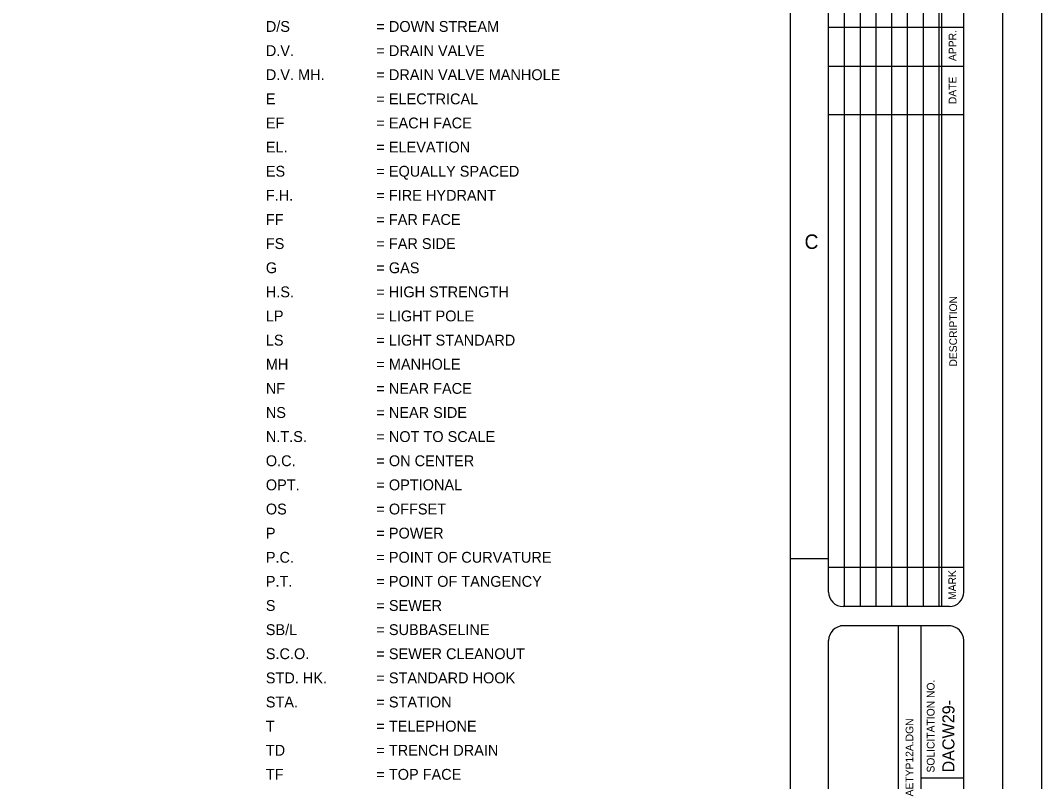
# Model space of a CAD drawing. Extents: x 22369.62 to 22373.29, y 22369.62 to 22372.46.
# Drawn here: x 22372.185 to 22373.288, y 22370.797 to 22371.619 of the extents above; entities that cross this region are included whole.
import ezdxf

# ---------------------------------------------------------------- set-up
doc = ezdxf.new("R2010")
doc.units = 0
for name, color, linetype in [('Level 1', 7, 'Continuous'), ('Level 10', 7, 'Continuous'), ('Level 2', 7, 'Continuous'), ('Level 4', 7, 'Continuous'), ('Level 7', 7, 'Continuous'), ('Level 9', 7, 'Continuous')]:
    doc.layers.add(name, color=color, linetype=linetype)

msp = doc.modelspace()

# ---------------------------------------------------------------- linework, layer by layer
at = {"layer": 'Level 1'}
for p, q in [((22373.075, 22372.2363), (22373.075, 22370.9863)), ((22373.092, 22372.2363), (22373.092, 22370.9863)), ((22373.109, 22372.2363), (22373.109, 22370.9863)), ((22373.126, 22372.2363), (22373.126, 22370.9863)), ((22373.143, 22372.2363), (22373.143, 22370.9863)), ((22373.16, 22372.2363), (22373.16, 22370.9863)), ((22373.177, 22372.2363), (22373.177, 22370.9863)), ((22373.18, 22372.2363), (22373.18, 22370.9863)), ((22373.204, 22371.6113), (22373.058, 22371.6113)), ((22373.1884, 22370.9863), (22373.0736, 22370.9863)), ((22373.19, 22370.9653), (22373.071, 22370.9653)), ((22373.133, 22370.9653), (22373.133, 22370.2673))]:
    msp.add_line(p, q, dxfattribs=at)
msp.add_lwpolyline([(22369.6213, 22372.4553), (22373.288, 22372.4553), (22373.288, 22369.6213), (22369.6213, 22369.6213)], close=True, dxfattribs=at)
for points in [[(22373.058, 22371.0019), (22373.058, 22372.2207)], [(22373.204, 22371.0019), (22373.204, 22372.2207)], [(22373.1884, 22370.9653), (22373.0736, 22370.9653)], [(22373.058, 22370.2829), (22373.058, 22370.9497)], [(22373.204, 22370.2829), (22373.204, 22370.9497)]]:
    msp.add_lwpolyline(points, dxfattribs=at)
for centre, start, end in [((22373.0736, 22371.0019), 180, 270), ((22373.1884, 22371.0019), 270, 0), ((22373.0736, 22370.9497), 90, 180), ((22373.1884, 22370.9497), 0, 90)]:
    msp.add_arc(centre, 0.0156, start, end, dxfattribs=at)
at = {"layer": 'Level 10'}
msp.add_line((22373.017, 22371.0383), (22373.058, 22371.0383), dxfattribs=at)
at = {"layer": 'Level 2'}
for p, q in [((22373.1576, 22370.9653), (22373.1576, 22370.6163)), ((22373.204, 22370.801), (22373.1576, 22370.801))]:
    msp.add_line(p, q, dxfattribs=at)
at = {"layer": 'Level 7'}
for p, q in [((22373.204, 22371.5693), (22373.058, 22371.5693)), ((22373.204, 22371.5172), (22373.058, 22371.5172)), ((22373.204, 22371.0283), (22373.058, 22371.0283))]:
    msp.add_line(p, q, dxfattribs=at)
at = {"layer": 'Level 9'}
msp.add_line((22373.246, 22369.6633), (22373.246, 22372.4133), dxfattribs=at)
msp.add_lwpolyline([(22373.017, 22369.6633), (22373.017, 22372.4133)], dxfattribs=at)

# ---------------------------------------------------------------- texts
at = {"layer": 'Level 1'}
for s, height, p in [('APPR.', 0.00833, (22373.196, 22371.5751)), ('DATE', 0.00833, (22373.196, 22371.5286)), ('DESCRIPTION', 0.008333, (22373.1967, 22371.2453)), ('MARK', 0.00833, (22373.1957, 22370.9934)), ('SOLICITATION NO.', 0.008334, (22373.1724, 22370.8071)), ('AETYP12A.DGN', 0.008333, (22373.1495, 22370.7813))]:
    msp.add_text(s, height=height, rotation=90, dxfattribs=at).set_placement(p)
msp.add_text('C', height=0.0156, dxfattribs=at).set_placement((22373.032, 22371.3723))
at = {"layer": 'Level 4'}
for s, height, p in [('D/S', 0.0117, (22372.4503, 22371.6066)), ('= DOWN STREAM', 0.011698, (22372.5697, 22371.6066)), ('D.V.', 0.0117, (22372.4503, 22371.5805)), ('= DRAIN VALVE', 0.011698, (22372.5697, 22371.5805)), ('D.V. MH.', 0.0117, (22372.4503, 22371.5545)), ('= DRAIN VALVE MANHOLE', 0.011698, (22372.5697, 22371.5545)), ('E', 0.0117, (22372.4503, 22371.5284)), ('= ELECTRICAL', 0.011698, (22372.5697, 22371.5284)), ('EF', 0.0117, (22372.4503, 22371.5024)), ('= EACH FACE', 0.011698, (22372.5697, 22371.5024)), ('EL.', 0.0117, (22372.4503, 22371.4764)), ('= ELEVATION', 0.011698, (22372.5697, 22371.4764)), ('ES ', 0.0117, (22372.4503, 22371.4503)), ('= EQUALLY SPACED', 0.011698, (22372.5697, 22371.4503)), ('F.H.', 0.0117, (22372.4503, 22371.4243)), ('= FIRE HYDRANT', 0.011698, (22372.5697, 22371.4243)), ('FF', 0.0117, (22372.4503, 22371.3982)), ('= FAR FACE', 0.0117, (22372.5697, 22371.3982)), ('FS', 0.0117, (22372.4503, 22371.3722)), ('= FAR SIDE', 0.0117, (22372.5697, 22371.3722)), ('G', 0.0117, (22372.4503, 22371.3461)), ('= GAS', 0.0117, (22372.5697, 22371.3461)), ('H.S.', 0.0117, (22372.4503, 22371.3201)), ('= HIGH STRENGTH', 0.011698, (22372.5697, 22371.3201)), ('LP ', 0.0117, (22372.4503, 22371.2941)), ('= LIGHT POLE', 0.011698, (22372.5697, 22371.2941)), ('LS', 0.0117, (22372.4503, 22371.268)), ('= LIGHT STANDARD', 0.011698, (22372.5697, 22371.268)), ('MH ', 0.0117, (22372.4503, 22371.242)), ('= MANHOLE', 0.0117, (22372.5697, 22371.242)), ('NF', 0.0117, (22372.4503, 22371.2159)), ('= NEAR FACE', 0.011698, (22372.5697, 22371.2159)), ('NS', 0.0117, (22372.4503, 22371.1899)), ('= NEAR SIDE', 0.011698, (22372.5697, 22371.1899)), ('N.T.S.', 0.0117, (22372.4503, 22371.1639)), ('= NOT TO SCALE', 0.011698, (22372.5697, 22371.1639)), ('O.C.', 0.0117, (22372.4503, 22371.1378)), ('= ON CENTER', 0.011698, (22372.5697, 22371.1378)), ('OPT.', 0.0117, (22372.4503, 22371.1118)), ('= OPTIONAL', 0.0117, (22372.5697, 22371.1118)), ('OS', 0.0117, (22372.4503, 22371.0857)), ('= OFFSET', 0.0117, (22372.5697, 22371.0857)), ('P', 0.0117, (22372.4503, 22371.0597)), ('= POWER', 0.0117, (22372.5697, 22371.0597)), ('P.C.', 0.0117, (22372.4503, 22371.0336)), ('= POINT OF CURVATURE', 0.011698, (22372.5697, 22371.0336)), ('P.T.', 0.0117, (22372.4503, 22371.0076)), ('= POINT OF TANGENCY', 0.011698, (22372.5697, 22371.0076)), ('S', 0.0117, (22372.4503, 22370.9816)), ('= SEWER', 0.0117, (22372.5697, 22370.9816)), ('SB/L', 0.0117, (22372.4503, 22370.9555)), ('= SUBBASELINE', 0.011698, (22372.5697, 22370.9555)), ('S.C.O.', 0.0117, (22372.4503, 22370.9295)), ('= SEWER CLEANOUT', 0.011698, (22372.5697, 22370.9295)), ('STD. HK.', 0.0117, (22372.4503, 22370.9034)), ('= STANDARD HOOK', 0.011698, (22372.5697, 22370.9034)), ('STA.', 0.0117, (22372.4503, 22370.8774)), ('= STATION', 0.0117, (22372.5697, 22370.8774)), ('T', 0.0117, (22372.4503, 22370.8514)), ('= TELEPHONE', 0.011698, (22372.5697, 22370.8514)), ('TD', 0.0117, (22372.4503, 22370.8253)), ('= TRENCH DRAIN', 0.011698, (22372.5697, 22370.8253)), ('TF', 0.0117, (22372.4503, 22370.7993)), ('= TOP FACE', 0.0117, (22372.5697, 22370.7993))]:
    msp.add_text(s, height=height, dxfattribs=at).set_placement(p)
at = {"layer": 'Level 7'}
msp.add_text('DACW29-', height=0.013, rotation=90, dxfattribs=at).set_placement((22373.1939, 22370.8072))

doc.saveas('drawing.dxf')
